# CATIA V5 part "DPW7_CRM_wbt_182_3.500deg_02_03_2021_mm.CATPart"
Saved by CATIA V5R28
Part number: DPW7_CRM_wbt_182_3.500deg_02_03_2021
Bounding box of the stored display mesh (mm): x 2349.5 to 66711.891, y 0 to 29462.352, z 2310.119 to 8715.756
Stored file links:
  Z:\Scratch\04_CAD_Allgemein\Flight2Jig\Output\DPW-7\CATPart\DPW7_CRM_wbt_182_3.500deg_02_03_2021.CATPart
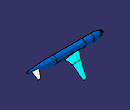
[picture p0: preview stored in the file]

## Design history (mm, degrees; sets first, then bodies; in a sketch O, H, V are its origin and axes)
Set1
  DatumSurface1 "Clean_Wing"
  DatumSurface2 "Fuselage"
  DatumSurface3 "HTP"
  DatumSurface4 "Symmetry"
  DatumSurface5 "Farfield"
Body1 (main body)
